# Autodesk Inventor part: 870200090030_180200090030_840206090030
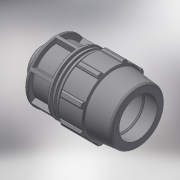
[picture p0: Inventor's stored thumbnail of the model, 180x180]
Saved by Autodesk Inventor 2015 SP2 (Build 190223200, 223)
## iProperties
Created: 2017-02
Part Number: 870200090030_180200090030_840206090030
Material: Generic
Description: PLASSON MALE ADAPTOR 90-3"
Document SubType Name: Modeling
Designer: KIM
Mass: 964.158 g
Surface Area: 1468.9 cm^2
Volume: 964.158 cm^3
Density: 1 g/cm^3
Appearance: Default
Author: KIM
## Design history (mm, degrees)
derived "87020.ipt"
feature "Solid1::87020.ipt"
tag "TaggingFeature1"
body "Solid1"
other parameters: "d4" = 33.14286, "d5" = 58, "d7" = 152, "d8" = 114, "d9" = 33.14286, "d11" = 6.62857, "d12" = 121.6, "d13" = 120 deg, "d14" = 117, "d15" = 6 deg, "d16" = 136.8, "d18" = 4.5, "d19" = 35 deg, "d20" = 17.5 deg, "d21" = 141.36, "d23" = 0, "d25" = 360 deg, "d27" = 3.04, "d34" = 7.6, "d36" = 0, "d42" = 58, "d43" = 4.56, "d46" = 2.7, "d49" = 169, "d51" = 232, "d52" = 33, "d53" = 1.8, "d55" = 360 deg, "d57" = 87.884, "d58" = 61.5188, "d59" = 46.4, "d61" = 134.064, "d62" = 4.66857, "d63" = 4.66857, "d66" = 9.33714, "E_" = 152, "H_" = 232, "l_" = 169, "l_2" = 33, "R_" = 87.884, "d60" = 23.34286
